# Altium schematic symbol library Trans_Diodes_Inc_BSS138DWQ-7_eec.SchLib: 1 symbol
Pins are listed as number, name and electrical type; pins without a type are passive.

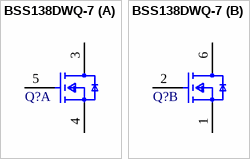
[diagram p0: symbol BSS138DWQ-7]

## BSS138DWQ-7
designator Q?  (value not drawn)
part A pins: 3 D1, 4 S1, 5 G1
part B pins: 1 S2, 2 G2, 6 D2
